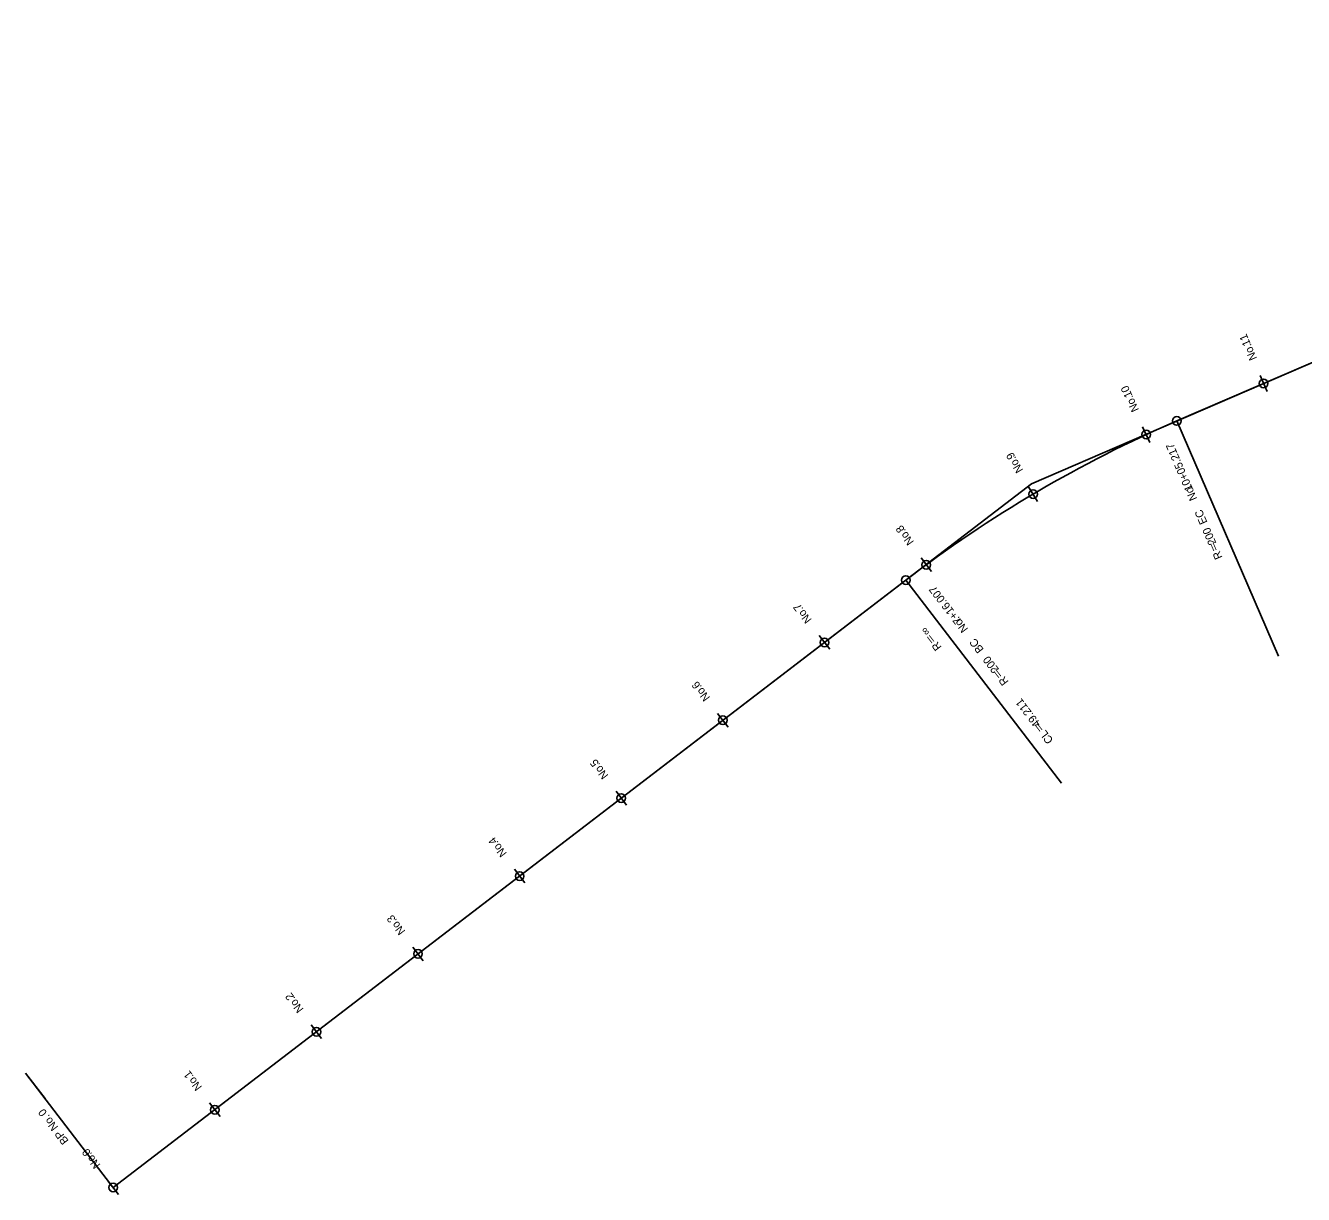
# Model space of a CAD drawing. Extents: x 46574 to 46965, y 10721 to 11034.
# Drawn here: x 46573.7 to 46773.3, y 10721.4 to 10904 of the extents above; entities that cross this region are included whole.
import ezdxf

# ---------------------------------------------------------------- set-up
doc = ezdxf.new("R2010")
doc.units = 0
for name, color, linetype in [('Default', 7, 'Continuous'), ('河川_通常部（地理院地図Vector）', 7, 'Continuous'), ('等高線等深線_等高線_計曲線通常部（地理院地図Vector）', 7, 'Continuous'), ('道路_通常部_通常部（地理院地図Vector）', 7, 'Continuous')]:
    doc.layers.add(name, color=color, linetype=linetype)

msp = doc.modelspace()

# ---------------------------------------------------------------- linework, layer by layer
at = {"layer": 'Default'}
for p, q in [((46730.82, 10832.46), (46896.47, 10904.04)), ((46767.09, 10848.13), (46767.09, 10848.13)), ((46753.52, 10842.27), (46753.52, 10842.27)), ((46753.52, 10842.27), (46769.39, 10805.55)), ((46748.76, 10840.14), (46748.76, 10840.14)), ((46587.37, 10722.52), (46730.82, 10832.46)), ((46731.07, 10830.84), (46731.07, 10830.84)), ((46714.39, 10819.81), (46714.39, 10819.81)), ((46711.19, 10817.42), (46711.19, 10817.42)), ((46711.19, 10817.42), (46735.53, 10785.67)), ((46698.49, 10807.68), (46698.49, 10807.68)), ((46682.62, 10795.51), (46682.62, 10795.51)), ((46666.74, 10783.35), (46666.74, 10783.35)), ((46650.87, 10771.18), (46650.87, 10771.18)), ((46634.99, 10759.02), (46634.99, 10759.02)), ((46619.12, 10746.85), (46619.12, 10746.85)), ((46586.96, 10723.05), (46573.68, 10740.37)), ((46573.68, 10740.37), (46576.73, 10736.41)), ((46603.25, 10734.68), (46603.25, 10734.68)), ((46587.37, 10722.52), (46587.37, 10722.52)), ((46587.37, 10722.52), (46587.37, 10722.52))]:
    msp.add_line(p, q, dxfattribs=at)
for centre in [(46767.09, 10848.13), (46753.52, 10842.27), (46748.76, 10840.14), (46731.07, 10830.84), (46714.39, 10819.81), (46711.19, 10817.42), (46698.49, 10807.68), (46682.62, 10795.51), (46666.74, 10783.35), (46650.87, 10771.18), (46634.99, 10759.02), (46619.12, 10746.85), (46603.25, 10734.68), (46587.37, 10722.52), (46587.37, 10722.52)]:
    msp.add_circle(centre, 0.675, dxfattribs=at)
msp.add_arc((46832.86, 10658.68), 200, 113.3699, 127.4678, dxfattribs=at)
at = {"layer": '等高線等深線_等高線_計曲線通常部（地理院地図Vector）'}
for p, q in [((46753.52, 10842.27), (46829.19, 10874.97)), ((46587.37, 10722.52), (46711.19, 10817.42))]:
    msp.add_line(p, q, dxfattribs=at)
msp.add_arc((46832.86, 10658.68), 200, 113.3699, 127.4678, dxfattribs=at)
at = {"layer": '道路_通常部_通常部（地理院地図Vector）'}
for p, q in [((46766.56, 10849.37), (46767.63, 10846.9)), ((46748.19, 10841.36), (46749.33, 10838.91)), ((46730.38, 10832), (46731.75, 10829.68)), ((46713.59, 10820.9), (46715.19, 10818.73)), ((46697.67, 10808.75), (46699.31, 10806.61)), ((46681.79, 10796.59), (46683.44, 10794.44)), ((46665.92, 10784.42), (46667.56, 10782.28)), ((46650.05, 10772.25), (46651.69, 10770.11)), ((46634.17, 10760.09), (46635.81, 10757.94)), ((46618.3, 10747.92), (46619.94, 10745.78)), ((46602.42, 10735.75), (46604.07, 10733.61)), ((46586.55, 10723.59), (46588.19, 10721.44))]:
    msp.add_line(p, q, dxfattribs=at)

# ---------------------------------------------------------------- texts
at = {"layer": 'Default'}
for s, rotation, p in [('10+05.217', 113.3699, (46756.07, 10831.65)), ('EC\u3000No.', 113.3699, (46758.33, 10826.43)), ('200', 113.3699, (46759.72, 10823.2)), ('R＝', 113.3699, (46760.69, 10820.96)), ('7+16.007', 127.4678, (46719.97, 10811.1)), ('BC\u3000No.', 127.4678, (46723.43, 10806.59)), ('R＝∞', 127.4678, (46716.85, 10806.96)), ('200', 127.4678, (46725.82, 10803.47)), ('R＝', 127.4678, (46727.3, 10801.54)), ('49.211', 127.4678, (46732.32, 10794.99)), ('CL＝', 127.4678, (46734.3, 10792.41)), ('0', 127.4678, (46577.11, 10734.22)), ('BP No.', 127.4678, (46580.48, 10729.83))]:
    msp.add_text(s, height=1.25, rotation=rotation, dxfattribs=at).set_placement(p)
at = {"layer": '河川_通常部（地理院地図Vector）'}
for s, rotation, p in [('11', 113.3699, (46765.11, 10854.29)), ('No.', 113.3699, (46766.08, 10852.05)), ('10', 114.8646, (46746.62, 10846.24)), ('No.', 114.8646, (46747.65, 10844.03)), ('9', 120.5942, (46728.33, 10836.7)), ('No.', 120.5942, (46729.57, 10834.6)), ('8', 126.3237, (46711.08, 10825.37)), ('No.', 126.3237, (46712.52, 10823.41)), ('7', 127.4678, (46695.07, 10813.17)), ('No.', 127.4678, (46696.55, 10811.24)), ('6', 127.4678, (46679.2, 10801)), ('No.', 127.4678, (46680.68, 10799.07)), ('5', 127.4678, (46663.32, 10788.84)), ('No.', 127.4678, (46664.8, 10786.9)), ('4', 127.4678, (46647.45, 10776.67)), ('No.', 127.4678, (46648.93, 10774.74)), ('3', 127.4678, (46631.57, 10764.5)), ('No.', 127.4678, (46633.06, 10762.57)), ('2', 127.4678, (46615.7, 10752.34)), ('No.', 127.4678, (46617.18, 10750.4)), ('1', 127.4678, (46599.83, 10740.17)), ('No.', 127.4678, (46601.31, 10738.24)), ('0', 127.4678, (46583.95, 10728.01)), ('No.', 127.4678, (46585.43, 10726.07))]:
    msp.add_text(s, height=1.25, rotation=rotation, dxfattribs=at).set_placement(p)

doc.saveas('drawing.dxf')
